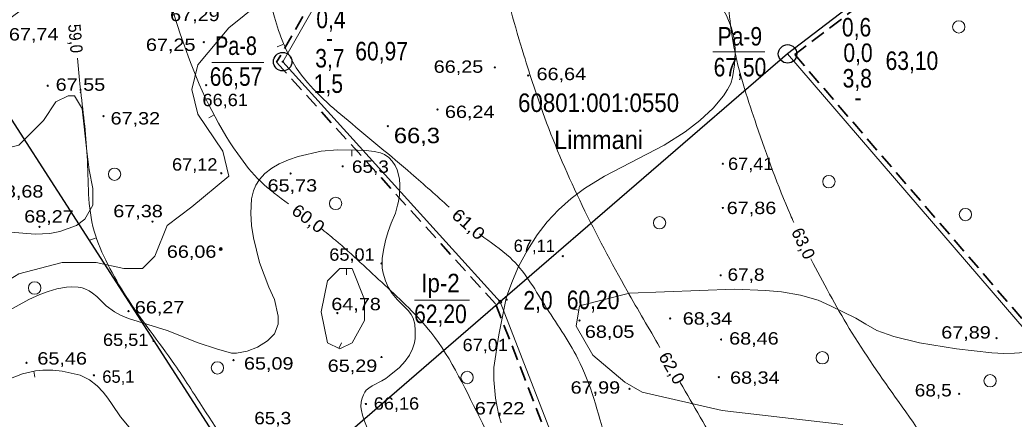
# Model space of a CAD drawing. Extents: x 628176 to 629009, y 6439913 to 6440496.
# Drawn here: x 628361.2 to 628522.3, y 6440223.6 to 6440288.3 of the extents above; entities that cross this region are included whole.
import ezdxf
from ezdxf.enums import TextEntityAlignment as Align

# ---------------------------------------------------------------- set-up
doc = ezdxf.new("R2010")
doc.units = 0
doc.header["$LTSCALE"] = 0.8
doc.linetypes.add('MEDIUM_DASHED', pattern=[4.5, 3, -1.5])
for name, color, linetype, lineweight in [('1', 7, 'Continuous', 13), ('11', 7, 'Continuous', 13), ('12', 7, 'Continuous', 13), ('14', 7, 'Continuous', 25), ('16', 7, 'Continuous', 13), ('21', 7, 'MEDIUM_DASHED', 35), ('3', 7, 'Continuous', 13)]:
    doc.layers.add(name, color=color, linetype=linetype, lineweight=lineweight)
doc.layers.add('23', color=7, linetype='Continuous')

msp = doc.modelspace()

# ---------------------------------------------------------------- hatches: boundary and pattern name
at = {"layer": '1'}
for points in [[(628391.0521, 6440284.6856, 1), (628390.8521, 6440284.6856, 1)], [(628403.8571, 6440281.5233, 1), (628403.6571, 6440281.5233, 1)], [(628438.2395, 6440280.5972, 1), (628438.0395, 6440280.5972, 1)], [(628443.6522, 6440279.2736, 1), (628443.4522, 6440279.2736, 1)], [(628365.7604, 6440277.6227, 1), (628365.5604, 6440277.6227, 1)], [(628391.443, 6440277.7215, 1), (628391.243, 6440277.7215, 1)], [(628428.9363, 6440273.7716, 1), (628428.7363, 6440273.7716, 1)], [(628374.8005, 6440272.701, 1), (628374.6005, 6440272.701, 1)], [(628420.901, 6440271.068, 1), (628420.701, 6440271.068, 1)], [(628413.5789, 6440264.571, 1), (628413.3789, 6440264.571, 1)], [(628475.1872, 6440264.9999, 1), (628474.9872, 6440264.9999, 1)], [(628393.9033, 6440263.4465, 1), (628393.7033, 6440263.4465, 1)], [(628405.1397, 6440263.4104, 1), (628404.9397, 6440263.4104, 1)], [(628475.1872, 6440257.8215, 1), (628474.9872, 6440257.8215, 1)], [(628364.4348, 6440254.7595, 1), (628364.2348, 6440254.7595, 1)], [(628382.7448, 6440255.6083, 1), (628382.5448, 6440255.6083, 1)], [(628393.9618, 6440251.1771, 1), (628393.4618, 6440251.1771, 1)], [(628393.8118, 6440251.1771, 1), (628393.6118, 6440251.1771, 1)], [(628449.2429, 6440250.0268, 1), (628449.0429, 6440250.0268, 1)], [(628419.8588, 6440248.8468, 1), (628419.6588, 6440248.8468, 1)], [(628474.84, 6440246.9155, 1), (628474.64, 6440246.9155, 1)], [(628440.1553, 6440242.987, 1), (628439.9553, 6440242.987, 1)], [(628378.8475, 6440241.1225, 1), (628378.6475, 6440241.1225, 1)], [(628412.7096, 6440240.8029, 1), (628412.5096, 6440240.8029, 1)], [(628466.6607, 6440239.9368, 1), (628466.4607, 6440239.9368, 1)], [(628451.9673, 6440239.6029, 1), (628451.7673, 6440239.6029, 1)], [(628474.9005, 6440236.5251, 1), (628474.7005, 6440236.5251, 1)], [(628519.5719, 6440236.7466, 1), (628519.3719, 6440236.7466, 1)], [(628382.9229, 6440236.2953, 1), (628382.7229, 6440236.2953, 1)], [(628419.867, 6440233.686, 1), (628419.667, 6440233.686, 1)], [(628362.3171, 6440232.7556, 1), (628362.1171, 6440232.7556, 1)], [(628395.8714, 6440233.1893, 1), (628395.6714, 6440233.1893, 1)], [(628373.2504, 6440230.7249, 1), (628373.0504, 6440230.7249, 1)], [(628474.5567, 6440230.4293, 1), (628474.3567, 6440230.4293, 1)], [(628460.0752, 6440228.5406, 1), (628459.8752, 6440228.5406, 1)], [(628513.5144, 6440227.7229, 1), (628513.3144, 6440227.7229, 1)], [(628417.341, 6440226.0788, 1), (628417.141, 6440226.0788, 1)], [(628442.8836, 6440224.7819, 1), (628442.6836, 6440224.7819, 1)]]:
    msp.add_hatch(color=256, dxfattribs=at).paths.add_polyline_path(points)

# ---------------------------------------------------------------- linework, layer by layer
for centre, radius in [((628513.3479, 6440287.1442), 1), ((628390.9521, 6440284.6856), 0.1), ((628403.7571, 6440281.5233), 0.1), ((628438.1395, 6440280.5972), 0.1), ((628443.5522, 6440279.2736), 0.1), ((628365.6604, 6440277.6227), 0.1), ((628391.343, 6440277.7215), 0.1), ((628428.8363, 6440273.7716), 0.1), ((628374.7005, 6440272.701), 0.1), ((628420.801, 6440271.068), 0.1), ((628376.4896, 6440263.2853), 1), ((628413.4789, 6440264.571), 0.1), ((628475.0872, 6440264.9999), 0.1), ((628393.8033, 6440263.4465), 0.1), ((628405.0397, 6440263.4104), 0.1), ((628492.2895, 6440262.0874), 1), ((628412.334, 6440258.5558), 1), ((628475.0872, 6440257.8215), 0.1), ((628514.4142, 6440256.7562), 1), ((628464.8336, 6440255.4233), 1), ((628364.3348, 6440254.7595), 0.1), ((628382.6448, 6440255.6083), 0.1), ((628393.7118, 6440251.1771), 0.25), ((628393.7118, 6440251.1771), 0.1), ((628449.1429, 6440250.0268), 0.1), ((628419.7588, 6440248.8468), 0.1), ((628474.74, 6440246.9155), 0.1), ((628363.5458, 6440244.8652), 1), ((628440.0553, 6440242.987), 0.1), ((628378.7475, 6440241.1225), 0.1), ((628412.6096, 6440240.8029), 0.1), ((628466.5607, 6440239.9368), 0.1), ((628451.8673, 6440239.6029), 0.1), ((628474.8005, 6440236.5251), 0.1), ((628519.4719, 6440236.7466), 0.1), ((628382.8229, 6440236.2953), 0.1), ((628419.767, 6440233.686), 0.1), ((628491.2233, 6440233.5653), 1), ((628362.2171, 6440232.7556), 0.1), ((628393.1672, 6440231.9214), 1), ((628395.7714, 6440233.1893), 0.1), ((628373.1504, 6440230.7249), 0.1), ((628433.6459, 6440230.3665), 1), ((628474.4567, 6440230.4293), 0.1), ((628518.4126, 6440229.8334), 1), ((628459.9752, 6440228.5406), 0.1), ((628513.4144, 6440227.7229), 0.1), ((628417.241, 6440226.0788), 0.1), ((628442.7836, 6440224.7819), 0.1)]:
    msp.add_circle(centre, radius, dxfattribs=at)
at = {"layer": '11'}
for points in [[(628595.11, 6440426.87), (628573.75, 6440350.05), (628485.59, 6440282.78), (628547.63, 6440210.77)], [(628479.31, 6440413.61), (628403.76, 6440281.52), (628439.01, 6440242.62), (628472.21, 6440157.1)]]:
    msp.add_lwpolyline(points, dxfattribs=at)
at = {"layer": '12'}
for p, q in [((628473.47, 6440283.13), (628481.9, 6440283.13)), ((628392.25, 6440281.37), (628400.68, 6440281.37)), ((628425.12, 6440242.9), (628434.02, 6440242.9))]:
    msp.add_line(p, q, dxfattribs=at)
at = {"layer": '12', "lineweight": 25}
for centre in [(628485.5919, 6440282.7768), (628403.7571, 6440281.5233)]:
    msp.add_circle(centre, 1.5, dxfattribs=at)
at = {"layer": '12'}
msp.add_circle((628439.0143, 6440242.6174), 0.25, dxfattribs=at)
at = {"layer": '14'}
for points in [[(628595.11, 6440426.87), (628573.75, 6440350.05), (628485.59, 6440282.78)], [(628326.62, 6440323.6), (628400.29, 6440209.22), (628472.21, 6440157.1), (628497.5, 6440118.54), (628498.85, 6440116.47)], [(628485.59, 6440282.78), (628439.01, 6440242.62), (628400.29, 6440209.22)]]:
    msp.add_lwpolyline(points, dxfattribs=at)
at = {"layer": '16'}
for p, q in [((628402.88, 6440283.91), (628403.8, 6440284.3)), ((628391.78, 6440272.42), (628392.66, 6440272.9)), ((628372.45, 6440252.63), (628373.42, 6440252.91))]:
    msp.add_line(p, q, dxfattribs=at)
for points in [[(628523.86, 6440425.63), (628523.12, 6440415.76), (628522.56, 6440410.73), (628519.12, 6440396.74), (628513.8, 6440381.86), (628510.45, 6440374.81), (628499.31, 6440356.42), (628494.72, 6440347.58), (628488, 6440335.91), (628479.91, 6440315.37), (628477.03, 6440304.26), (628475.97, 6440294.36), (628477.03, 6440283.22), (628480.57, 6440271.2), (628486.05, 6440256.7), (628486.58, 6440255.49)], [(628500.95, 6440423.21), (628492.76, 6440414.83), (628485.87, 6440407.94), (628478.97, 6440401.05), (628470.41, 6440392.85), (628466.49, 6440387.45), (628459.04, 6440376.65), (628449.92, 6440361.56), (628445.26, 6440350.76), (628442.84, 6440342.93), (628439.11, 6440323.75), (628438.18, 6440304.38), (628440.79, 6440289.66), (628442.84, 6440282.59), (628446.19, 6440272.53), (628459.6, 6440244.4), (628464.91, 6440235.24)], [(628417.51, 6440405.33), (628413.04, 6440391.73), (628407.64, 6440376.09), (628405.21, 6440367.15), (628402.23, 6440348.89), (628401.3, 6440336.6), (628400.74, 6440326.92), (628400.74, 6440316.86), (628400.56, 6440301.21), (628402.42, 6440288.73), (628405.96, 6440280.54), (628414.34, 6440271.97), (628424.59, 6440263.4), (628430.76, 6440257.95)], [(628377.28, 6440389.13), (628377.09, 6440364.17), (628380.07, 6440319.28), (628382.3, 6440305.31), (628388.08, 6440283.33), (628396.46, 6440266.57), (628400.19, 6440262.1), (628404.68, 6440258.52)], [(628370.47, 6440282.1), (628370.94, 6440277.37), (628372.06, 6440266.2), (628373.18, 6440254.09), (628375.41, 6440248.69), (628378.39, 6440243.47), (628386.22, 6440232.48), (628390.87, 6440225.4), (628398.32, 6440213.3), (628399.81, 6440209.39), (628399.63, 6440203.43), (628398.5, 6440197.6), (628398.32, 6440196.1)], [(628409.9, 6440254.58), (628412.29, 6440252.6), (628420.3, 6440245.33), (628427.75, 6440237.7), (628436.13, 6440222.98), (628444.52, 6440204.92), (628447.68, 6440184.24), (628451.78, 6440164.12), (628460.72, 6440143.45), (628472.64, 6440122.77), (628478.97, 6440106.2), (628480.84, 6440088.32)], [(628435.66, 6440253.61), (628435.76, 6440253.53), (628440.6, 6440249.8), (628446.19, 6440242.17), (628451.59, 6440233.41), (628456.06, 6440220.19), (628460.16, 6440203.24), (628465, 6440185.73), (628472.27, 6440163.38), (628475.81, 6440154.44), (628479.91, 6440135.81), (628483.63, 6440121.84), (628486.42, 6440113.09), (628492.01, 6440103.59)], [(628489.38, 6440249.57), (628495.6, 6440238.31), (628503.56, 6440226.46), (628524.07, 6440201.18), (628533.26, 6440193.04), (628542.28, 6440184.38)], [(628468.19, 6440229.57), (628474.69, 6440218.33), (628482.33, 6440205.1), (628494.06, 6440185.17), (628506.35, 6440170.08), (628513.25, 6440161.52), (628522, 6440153.51)]]:
    msp.add_spline(points, degree=3, dxfattribs=at)
at = {"layer": '21'}
for points in [[(628595.48, 6440425.23), (628574.45, 6440349.57), (628486.75, 6440282.66), (628547.03, 6440212.69)], [(628476.73, 6440410.71), (628402.77, 6440281.42), (628438.32, 6440242.19), (628470.2, 6440160.05)]]:
    msp.add_lwpolyline(points, dxfattribs=at)
at = {"layer": '3'}
for p, q in [((628476.98, 6440281), (628476.66, 6440278.98)), ((628476.38, 6440278), (628476.66, 6440278.98)), ((628415.88, 6440267.21), (628412.63, 6440267.26)), ((628414.96, 6440266.22), (628414.98, 6440267.22)), ((628455.93, 6440263), (628465.59, 6440268)), ((628452.67, 6440261), (628455.93, 6440263)), ((628422.51, 6440258.86), (628422.67, 6440259.92)), ((628422.01, 6440257), (628422.37, 6440258.26)), ((628422.51, 6440258.86), (628422.37, 6440258.26)), ((628422.01, 6440257), (628421.35, 6440255.36)), ((628355, 6440254.32), (628363.65, 6440253.56)), ((628366, 6440253.69), (628363.65, 6440253.56)), ((628414.1, 6440247), (628414.1, 6440248)), ((628442, 6440248.36), (628441, 6440246)), ((628420.41, 6440246), (628420.05, 6440247.24)), ((628367.16, 6440244.72), (628368.71, 6440245)), ((628368.71, 6440245), (628369.48, 6440245.05)), ((628370.6, 6440245), (628369.48, 6440245.05)), ((628371.23, 6440244.88), (628370.6, 6440245)), ((628371.66, 6440244.74), (628371.23, 6440244.88)), ((628372.36, 6440244.38), (628371.66, 6440244.74)), ((628440.27, 6440244), (628441, 6440246)), ((628372.94, 6440244), (628372.36, 6440244.38)), ((628373.61, 6440243.46), (628372.94, 6440244)), ((628374.11, 6440243), (628373.61, 6440243.46)), ((628440, 6440243.22), (628438.76, 6440237.29)), ((628440.27, 6440244), (628440, 6440243.22)), ((628490.53, 6440242.87), (628487.7, 6440243.68)), ((628450.76, 6440241.46), (628451.75, 6440241.29)), ((628451.3, 6440238.66), (628451.87, 6440242)), ((628492.53, 6440242), (628490.53, 6440242.87)), ((628492.53, 6440242), (628496.66, 6440240)), ((628385.03, 6440238), (628378.75, 6440239.93)), ((628496.66, 6440240), (628498.26, 6440239)), ((628507, 6440236), (628502.84, 6440237)), ((628413.31, 6440235.96), (628412.87, 6440235.07)), ((628507, 6440236), (628513, 6440235)), ((628513, 6440235), (628518.68, 6440234.36)), ((628363.6, 6440230.4), (628363.39, 6440231.37)), ((628363.66, 6440231.43), (628364.89, 6440231.58)), ((628366.47, 6440231.55), (628364.89, 6440231.58)), ((628368, 6440231.37), (628366.47, 6440231.55)), ((628373.67, 6440229), (628372.46, 6440230)), ((628374.63, 6440228), (628373.67, 6440229)), ((628438.27, 6440227), (628438, 6440230)), ((628438.27, 6440227), (628438.76, 6440224.19)), ((628416.44, 6440225.63), (628416.51, 6440225)), ((628416.67, 6440224.28), (628416.51, 6440225)), ((628438.76, 6440224.19), (628439.19, 6440223)), ((628475, 6440225), (628494.57, 6440222.74))]:
    msp.add_line(p, q, dxfattribs=at)
for points in [[(628371.31, 6440273.83), (628370, 6440276), (628369, 6440276), (628367, 6440275), (628365, 6440272), (628361, 6440268), (628357, 6440267), (628351.41, 6440267), (628350, 6440268), (628349, 6440271), (628350, 6440278), (628352, 6440283), (628354, 6440285), (628358.78, 6440288), (628367, 6440294), (628372, 6440299), (628376.27, 6440304), (628378.53, 6440307), (628381.54, 6440312)], [(628467, 6440296), (628469, 6440295.49), (628470.2, 6440295), (628471.25, 6440294.46), (628472.62, 6440293.46), (628473, 6440293.07), (628473.88, 6440292), (628474.57, 6440291), (628475.71, 6440289), (628476.48, 6440287), (628476.98, 6440285), (628477.09, 6440283.56), (628477.08, 6440282.88), (628476.98, 6440281)], [(628351.82, 6440241.56), (628361, 6440247.17), (628368, 6440249), (628373.51, 6440249), (628378, 6440248), (628381, 6440248), (628383, 6440250), (628385, 6440255), (628389, 6440258), (628395, 6440263), (628394.03, 6440267), (628390, 6440273), (628389, 6440277), (628390, 6440281), (628395, 6440287), (628400, 6440291)], [(628476.38, 6440278), (628475.84, 6440277), (628475.2, 6440276), (628473.54, 6440274), (628471.39, 6440272), (628469, 6440270.13), (628465.59, 6440268)], [(628366, 6440253.69), (628367.65, 6440254), (628370.33, 6440255), (628371.66, 6440256), (628373, 6440258.29), (628373, 6440261), (628372.4, 6440264), (628371.98, 6440267), (628371.26, 6440273.9)], [(628412.63, 6440267.26), (628410, 6440267), (628406.28, 6440266.16)], [(628415.88, 6440267.21), (628417.27, 6440267.12), (628418.59, 6440266.97), (628419.59, 6440266.75), (628420.25, 6440266.47), (628420.95, 6440266), (628421.49, 6440265.42), (628422, 6440264.69), (628422.3, 6440264), (628422.59, 6440263), (628422.67, 6440262.48), (628422.73, 6440261.55), (628422.67, 6440259.92)], [(628393, 6440235), (628395.44, 6440234.3), (628396.28, 6440234.3), (628398, 6440234.62), (628399.65, 6440235.28), (628401.29, 6440236.3), (628402.45, 6440237.46), (628403, 6440239), (628403, 6440240.28), (628402.45, 6440243), (628401.52, 6440245), (628400, 6440249), (628399, 6440253), (628398.72, 6440255), (628398.61, 6440257), (628398.72, 6440259.28), (628399, 6440260.6), (628399.41, 6440261.53), (628400, 6440262.42), (628400.84, 6440263.39), (628402, 6440264.28), (628403.19, 6440265), (628404.71, 6440265.63), (628406.28, 6440266.16)], [(628442, 6440248.36), (628443.43, 6440251), (628445, 6440253.47), (628446.61, 6440255.56), (628448.46, 6440257.53), (628450.51, 6440259.38), (628452.67, 6440261)], [(628421.35, 6440255.36), (628420.85, 6440254), (628420.4, 6440252.53), (628420.07, 6440251)], [(628420.07, 6440251), (628419.9, 6440249.63), (628419.86, 6440248.67)], [(628556.82, 6440250.15), (628555.66, 6440249), (628554, 6440247.65), (628552.08, 6440246.3), (628550, 6440245), (628544.53, 6440242), (628537, 6440238.51), (628533.54, 6440237), (628530.82, 6440236), (628529, 6440235.47), (628527.11, 6440235), (628524, 6440234.44), (628522.35, 6440234.29), (628520.65, 6440234.26), (628518.68, 6440234.36)], [(628419.86, 6440248.67), (628419.9, 6440248.1), (628420.05, 6440247.24)], [(628362.6, 6440243), (628364.38, 6440243.79), (628365.76, 6440244.32), (628367.16, 6440244.72)], [(628420.41, 6440246), (628420.84, 6440245), (628421.49, 6440243.99), (628422.29, 6440243), (628423.33, 6440242)], [(628451.87, 6440242), (628459.98, 6440244), (628477, 6440244.65)], [(628477, 6440244.65), (628482, 6440244.48), (628484.61, 6440244.22), (628487.7, 6440243.68)], [(628354.39, 6440238), (628356.7, 6440239.57), (628358.98, 6440241), (628362.6, 6440243)], [(628378.75, 6440239.93), (628377.46, 6440240.48), (628376.51, 6440241), (628375.16, 6440242), (628374.43, 6440242.7), (628374.11, 6440243)], [(628423.33, 6440242), (628424.15, 6440241.15), (628424.59, 6440240.55)], [(628424.59, 6440240.55), (628424.88, 6440240), (628425.16, 6440239), (628425.25, 6440238)], [(628451.3, 6440238.66), (628454, 6440234), (628459.23, 6440229.61), (628462, 6440228), (628475, 6440225)], [(628498.26, 6440239), (628500.05, 6440238), (628502.84, 6440237)], [(628385.03, 6440238), (628390.07, 6440236), (628393, 6440235)], [(628425.25, 6440238), (628425.21, 6440236.67), (628425.11, 6440236), (628424.81, 6440235), (628424.29, 6440234), (628423.62, 6440233), (628422.68, 6440232), (628421, 6440230.62), (628420.45, 6440230.19), (628419.82, 6440229.8), (628419.3, 6440229.53), (628418.9, 6440229.33), (628418.25, 6440229), (628417.72, 6440228.66), (628417.3, 6440228.3), (628417.07, 6440228), (628416.83, 6440227.54), (628416.62, 6440227), (628416.49, 6440226.41), (628416.44, 6440225.63)], [(628438, 6440230), (628438, 6440232), (628438.76, 6440237.29)], [(628363.66, 6440231.43), (628361.57, 6440230.98), (628359.07, 6440230), (628357, 6440228.72), (628355.2, 6440227), (628353.8, 6440225), (628352.53, 6440223), (628351.1, 6440221)], [(628372.46, 6440230), (628370.9, 6440230.72), (628369.94, 6440230.98), (628368, 6440231.37)], [(628384.18, 6440218.37), (628381.18, 6440220), (628379.13, 6440222), (628377.48, 6440224), (628376.12, 6440226), (628375.42, 6440227), (628374.63, 6440228)], [(628416.67, 6440224.28), (628417, 6440223.3), (628417.45, 6440222.23), (628418, 6440221.18), (628419.31, 6440219.19), (628420.37, 6440217.83)]]:
    msp.add_lwpolyline(points, dxfattribs=at)
msp.add_lwpolyline([(628415, 6440236), (628417, 6440239.61), (628417, 6440243), (628415, 6440248), (628413, 6440248), (628411, 6440246), (628410, 6440241), (628411, 6440236), (628413, 6440235)], close=True, dxfattribs=at)

# ---------------------------------------------------------------- texts
at = {"layer": '1'}
for s, height, width, p in [('67,29', 2, 1.2, (628385.5, 6440288.09)), ('67,74', 2, 1.2, (628359.37, 6440284.95)), ('67,25', 2, 1.2, (628381.58, 6440283.27)), ('66,25', 2, 1.2, (628428.23, 6440279.72)), ('66,64', 2, 1.2, (628444.9, 6440278.53)), ('67,55', 2, 1.2, (628366.95, 6440276.81)), ('66,61', 2, 1.1, (628390.75, 6440274.32)), ('66,24', 2, 1.2, (628430.05, 6440272.4)), ('67,32', 2, 1.2, (628375.85, 6440271.35)), ('66,3', 2.5, 1.15, (628421.77, 6440268.32)), ('67,12', 2, 1.1, (628385.81, 6440263.88)), ('67,41', 2, 1.1, (628475.94, 6440263.98)), ('65,3', 2, 1.15, (628414.97, 6440263.52)), ('65,73', 2, 1.2, (628401.3, 6440260.47)), ('68,68', 2, 1.2, (628356.93, 6440259.51)), ('67,38', 2, 1.2, (628376.29, 6440256.32)), ('67,86', 2, 1.2, (628475.73, 6440256.84)), ('68,27', 2, 1.2, (628361.85, 6440255.46)), ('66,06', 2, 1.2, (628384.97, 6440249.76)), ('65,01', 2, 1.1, (628411.3, 6440249.28)), ('67,8', 2, 1.15, (628475.86, 6440246.04)), ('64,78', 2, 1.2, (628411.63, 6440241.26)), ('66,27', 2, 1.2, (628379.78, 6440240.74)), ('68,34', 2, 1.2, (628468.6, 6440238.93)), ('68,05', 2, 1.2, (628452.73, 6440236.79)), ('67,89', 2, 1.2, (628510.5, 6440236.67)), ('65,51', 2, 1.1, (628374.62, 6440235.48)), ('67,01', 2, 1.1, (628432.91, 6440234.64)), ('68,46', 2, 1.2, (628476.12, 6440235.7)), ('65,46', 2, 1.2, (628363.99, 6440232.46)), ('65,09', 2, 1.2, (628397.47, 6440231.65)), ('65,29', 2, 1.2, (628411.05, 6440231.27)), ('68,34', 2, 1.2, (628476.27, 6440229.36)), ('67,99', 2, 1.2, (628450.42, 6440227.75)), ('68,5', 2, 1.15, (628506.21, 6440227.3)), ('66,16', 2, 1.1, (628418.51, 6440225.16)), ('67,22', 2, 1.2, (628434.89, 6440224.38)), ('65,3', 2, 1.15, (628399.14, 6440222.79))]:
    msp.add_text(s, height=height, dxfattribs=dict(at, width=width)).set_placement(p)
for s, p in [('67,11', (628441.19, 6440250.7)), ('65,1', (628374.51, 6440229.51))]:
    msp.add_text(s, height=2, dxfattribs=at).set_placement(p)
at = {"layer": '11', "width": 0.85}
for s, p in [('0,6', (628496.775, 6440285.6)), ('-', (628497.01, 6440274.25))]:
    msp.add_text(s, height=3, dxfattribs=at).set_placement(p, align=Align.CENTER)
at = {"layer": '12'}
for s, width, p in [('0,4', 0.85, (628411.57, 6440286.94)), ('Pa-9', 0.85, (628477.865, 6440284.13)), ('Pa-8', 0.8, (628396.18, 6440282.61)), ('-', 0.85, (628411.345, 6440283.87)), ('3,7', 0.85, (628411.395, 6440280.58)), ('60,97', 0.85, (628419.785, 6440281.73)), ('0,0', 0.85, (628497.01, 6440281.47)), ('67,50', 0.85, (628477.87, 6440279.13)), ('63,10', 0.85, (628505.745, 6440280.18)), ('66,57', 0.85, (628396.19, 6440277.61)), ('3,8', 0.85, (628496.89, 6440277.33)), ('1,5', 0.85, (628411.16, 6440276.46)), ('Ip-2', 0.9, (628429.325, 6440244.17)), ('2,0', 0.85, (628445.135, 6440241.37)), ('60,20', 0.85, (628454.065, 6440241.44)), ('62,20', 0.85, (628429.32, 6440239.17))]:
    msp.add_text(s, height=3, dxfattribs=dict(at, width=width)).set_placement(p, align=Align.CENTER)
at = {"layer": '16'}
for s, rotation, width, p in [('59,0', 274.98, 0.9, (628369.175, 6440285.1868)), ('60,0', 323.293, 1.1, (628407.3073, 6440255.3103)), ('61,0', 318.44, 1.15, (628433.2066, 6440254.4418)), ('62,0', 300.071, 1.05, (628465.9724, 6440231.3961))]:
    msp.add_text(s, height=2, rotation=rotation, dxfattribs=dict(at, width=width)).set_placement(p, align=Align.CENTER)
msp.add_text('63,0', height=2, rotation=295.306, dxfattribs=at).set_placement((628487.2462, 6440251.6524), align=Align.CENTER)
at = {"layer": '23'}
for s, width, p in [('60801:001:0550', 0.9, (628454.955, 6440273.37)), ('Limmani', 0.95, (628454.955, 6440267.37))]:
    msp.add_text(s, height=3, dxfattribs=dict(at, width=width)).set_placement(p, align=Align.CENTER)

doc.saveas('drawing.dxf')
